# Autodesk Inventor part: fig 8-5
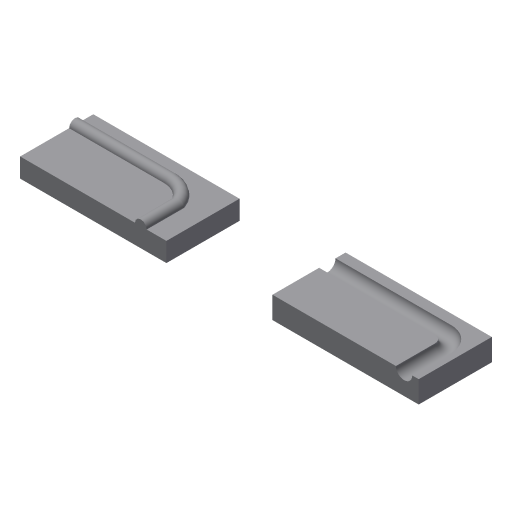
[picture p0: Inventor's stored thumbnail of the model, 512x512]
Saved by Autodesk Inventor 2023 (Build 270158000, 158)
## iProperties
Created: 2009-04
Part Number: fig 8-5
Document SubType Name: Modeling
Designer: Sham
Density: 1 g/cm^3
Material: Generic
Appearance: Default
Author: Sham
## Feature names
1. Extrusion1
2. Sweep5
3. Extrusion2
4. Sweep6
## Parameters: d0 = 6 mm, d1 = 0, d6 = 0, d7 = 5.25 mm, d8 = 0, d9 = 0, d10 = 0, d11 = 0
